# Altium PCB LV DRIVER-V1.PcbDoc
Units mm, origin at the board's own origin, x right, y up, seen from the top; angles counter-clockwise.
Board outline 70 x 80 mm, 2 copper layers (Top Layer, Bottom Layer); 48 components, 36 nets, 156 pads, 149 vias.
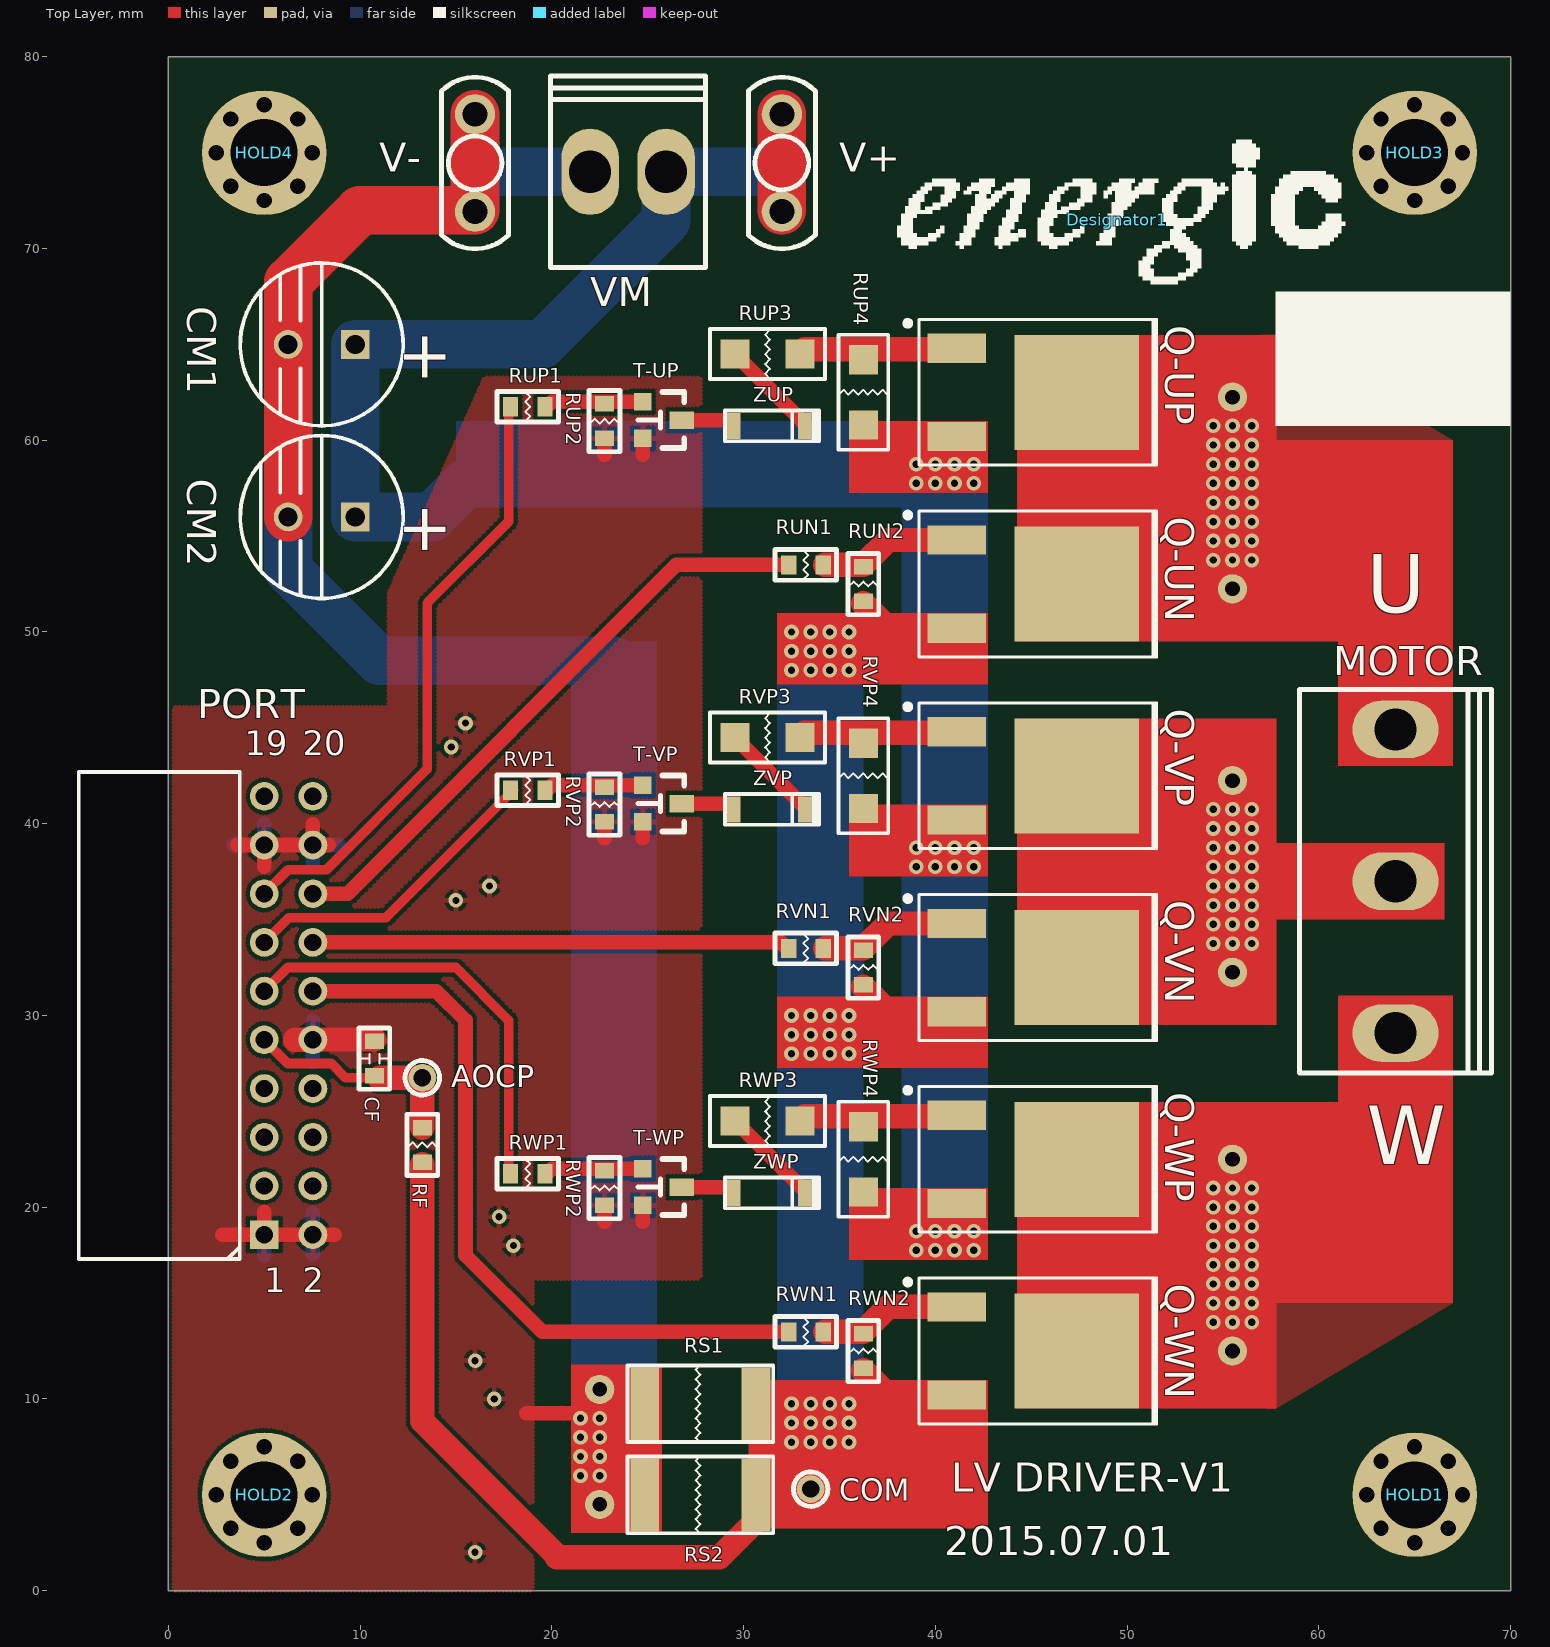
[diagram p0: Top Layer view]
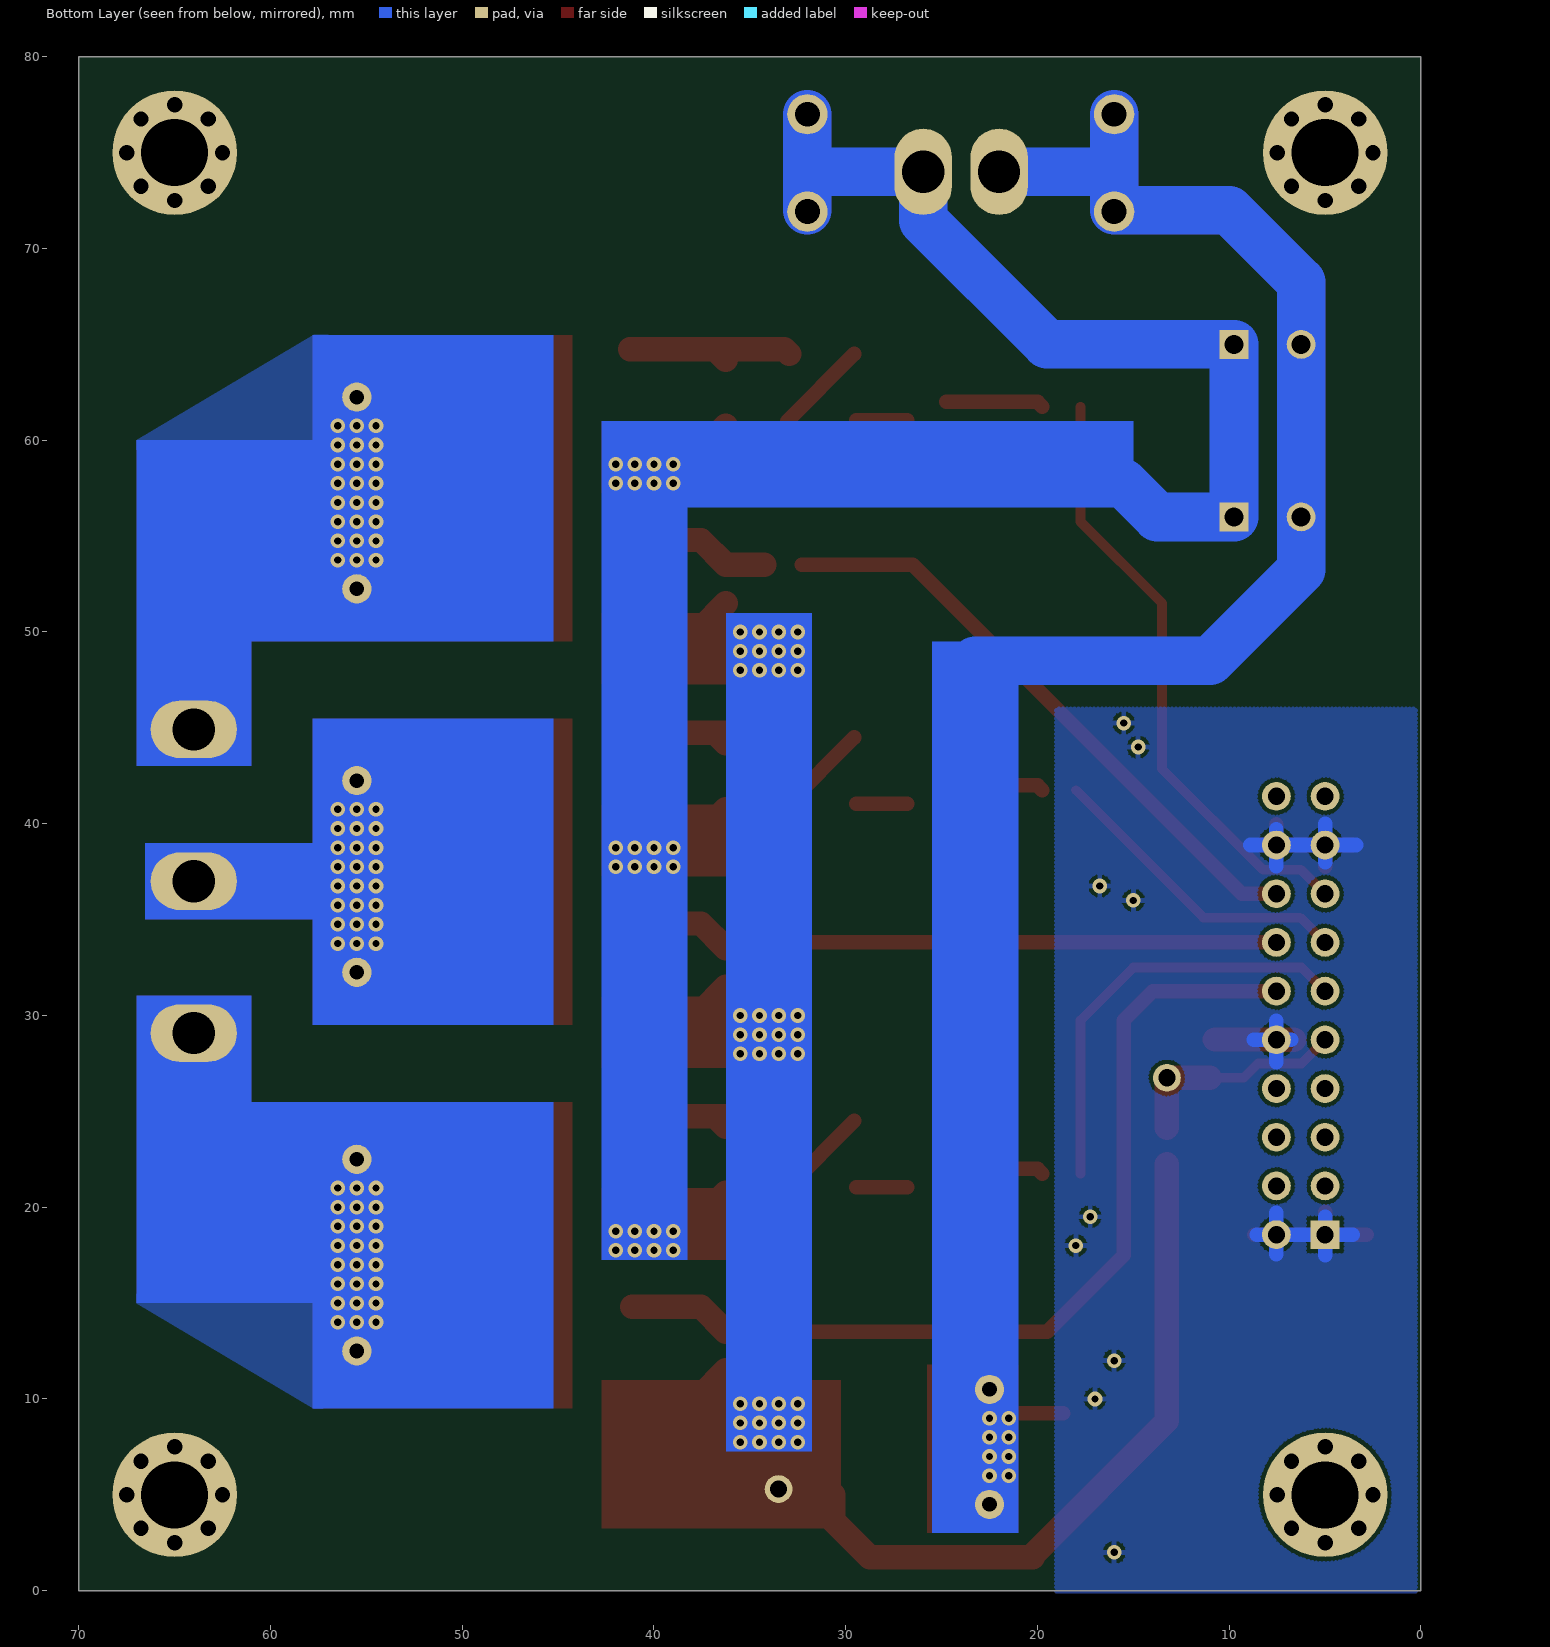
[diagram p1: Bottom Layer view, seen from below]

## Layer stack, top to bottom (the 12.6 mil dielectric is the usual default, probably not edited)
Top Layer: signal copper 0.0356
Dielectric: dielectric 0.32, FR-4, Dk 4.8
Bottom Layer: signal copper 0.0356

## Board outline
0,0 0,80 70,80 70,0

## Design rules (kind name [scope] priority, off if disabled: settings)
Clearance [All] p1: gap=0.203
MinimumSolderMaskSliver [All] p1: minsoldermaskwidth=0.127
PolygonConnect [All] p1: connectstyle=Relief reliefconductorwidth=0.254 reliefentries=4 polygonreliefangle="90 Angle"
RoutingVias [All] p1: holewidth=0.762 width=2.54 viastyle="Through Hole" minholewidth=0.203 minwidth=0.203 maxholewidth=0.711 maxwidth=1.27
SilkToSilkClearance [All] p1: silktosilkclearance=0.127
SilkscreenOverComponentPads [All] p1: minsilkscreentomaskgap=0
SolderMaskExpansion [All] p1: expansion=0.102
Width [All] p1: maxlimit=5.08 minlimit=0.254 preferedwidth=0.254
25 further rules are at their usual default settings.

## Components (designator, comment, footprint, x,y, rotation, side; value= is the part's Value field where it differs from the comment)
AOCP "" TP-R-0.9mm 13.25,26.75 r90 top
CF "1nF/50V/0603" C0603 10.75,27.75 r90 top
CM1 "220UF/35V/8*15" C-8MM-3.5PITCH 8,65 r270 top
CM2 "220UF/35V/8*15" C-8MM-3.5PITCH 8,56 r270 top
COM "" TP-R-0.9mm 33.5,5.3 r0 top
Designator1 "Comment" energic 49.5,71.5 r0 top
HOLD1 "TP" HOLD-3-6 65,5 r0 top
HOLD2 "TP" HOLD-3-6 5,5 r0 top locked
HOLD3 "TP" HOLD-3-6 65,75 r0 top
HOLD4 "TP" HOLD-3-6 5,75 r0 top
MOTOR "Header 5" CON-5-2P-3.96 64,37 r90 top
PORT "CON20/2.5/90" CON-2.54-2x20-90 5,18.57 r0 top locked
Q-UN "NMOS" TO-252 44.25,52.5 r180 top locked
Q-UP "PMOS" TO-252 44.25,62.5 r180 top locked
Q-VN "NMOS" TO-252 44.25,32.5 r180 top
Q-VP "PMOS" TO-252 44.25,42.5 r180 top
Q-WN "NMOS" TO-252 44.25,12.5 r180 top
Q-WP "PMOS" TO-252 44.25,22.5 r180 top
RF "100R/0603" R0603 13.25,23.25 r270 top
RS1 "0R1/2W" R2512 27.75,9.75 r180 top
RS2 "0R1/2W" R2512 27.75,5 r180 top
RUN1 "100/0603" R0603 33.25,53.5 r180 top
RUN2 "4.7K/0603" R0603 36.25,52.5 r270 top
RUP1 "1K/0603" R0603 18.75,61.75 r180 top
RUP2 "4.7K/0603" R0603 22.75,61 r270 top
RUP3 "100/1206" R1206 31.25,64.5 r0 top
RUP4 "470/1206" R1206 36.25,62.5 r270 top
RVN1 "100/0603" R0603 33.25,33.5 r180 top (schematic designator RUN1)
RVN2 "4.7K/0603" R0603 36.25,32.5 r270 top (schematic designator RUN2)
RVP1 "1K/0603" R0603 18.75,41.75 r180 top
RVP2 "4.7K/0603" R0603 22.75,41 r270 top (schematic designator RUP2)
RVP3 "100/1206" R1206 31.25,44.5 r0 top (schematic designator RUP3)
RVP4 "470/1206" R1206 36.25,42.5 r270 top (schematic designator RUP4)
RWN1 "100/0603" R0603 33.25,13.5 r180 top (schematic designator RUN1)
RWN2 "4.7K/0603" R0603 36.25,12.5 r270 top (schematic designator RUN2)
RWP1 "1K/0603" R0603 18.75,21.75 r180 top (schematic designator RUP1)
RWP2 "4.7K/0603" R0603 22.75,21 r270 top (schematic designator RUP2)
RWP3 "100/1206" R1206 31.25,24.5 r0 top (schematic designator RUP3)
RWP4 "470/1206" R1206 36.25,22.5 r270 top (schematic designator RUP4)
T-UP "MMBT4401" Q-MMBT4401 24.75,62 r180 top
T-VP "MMBT4401" Q-MMBT4401 24.75,42 r180 top (schematic designator T-UP)
T-WP "MMBT4401" Q-MMBT4401 24.75,22 r180 top (schematic designator T-UP)
V+ "(250T)" CON-P-850 32,77 r270 top
V- "(250T)" CON-P-850 16,77 r270 top
VM "Header 2" CON-2P-3.96 22,74 r180 top
ZUP "MMSZ 5242B T/R7" D-SOD123 29.5,60.75 r0 top
ZVP "MMSZ 5242B T/R7" D-SOD123 29.5,40.75 r0 top (schematic designator ZUP)
ZWP "MMSZ 5242B T/R7" D-SOD123 29.5,20.75 r0 top (schematic designator ZUP)

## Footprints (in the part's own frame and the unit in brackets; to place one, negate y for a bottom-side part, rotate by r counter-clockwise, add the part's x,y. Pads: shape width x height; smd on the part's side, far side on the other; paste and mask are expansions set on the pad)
C0603 [mm]
  rect 0.8x1 smd: 1(-0.9,0) 2(0.9,0)
  silkscreen extent -1.6,-0.8 1.6,0.8
C-8MM-3.5PITCH [mm]
  rect 1.5x1.5 hole 1: 1(0,1.75)
  round 1.5 hole 1: 2(0,-1.75)
  silkscreen extent -4.25,-4.25 4.25,4.25
CON-2.54-2x20-90 [mm] "Connector; Header; 10x2 Position; Right Angle"
  rect 1.5x1.5 hole 0.9: 1(0,0)
  round 1.5 hole 0.9: 2(2.54,0) 3(0,2.54) 4(2.54,2.54) 5(0,5.08) 6(2.54,5.08) 7(0,7.62) 8(2.54,7.62) 9(0,10.16) 10(2.54,10.16) 11(0,12.7) 12(2.54,12.7) 13(0,15.24) 14(2.54,15.24) 15(0,17.78) 16(2.54,17.78) 17(0,20.32) 18(2.54,20.32) 19(0,22.86) 20(2.54,22.86)
  silkscreen extent -9.67,-1.27 -1.27,24.13
CON-2P-3.96 [mm]
  oval 3x4.5 hole 2.2: 1(-3.96,0) 2(0,0)
  silkscreen extent -6.02,-5 2.06,5
CON-5-2P-3.96 [mm]
  oval 3x4.5 hole 2.2: 1(-7.92,0) 3(0,0) 5(7.92,0)
  silkscreen extent -10,-5 10,5
CON-P-850 [mm]
  round 2.1 hole 1.3: 1(0,0) 1(5.08,0)
  silkscreen extent -1.93,-1.75 7.01,1.75
D-SOD123 [mm]
  rect 0.7x1.35 smd: A(0,0) K(3.7,0)
  silkscreen extent -0.47,-0.8 4.43,0.8
energic [mm]
  silkscreen extent -11.48,-3.35 11.89,4.17
HOLD-3-6 [mm]
  round 1.2 hole 0.8: 1(-2.5,0) 1(-1.75,-1.75) 1(-1.75,1.75) 1(-0.004,2.5) 1(0,-2.5) 1(1.75,-1.75) 1(1.75,1.75) 1(2.5,0)
  round 6.5 hole 3.5: 1(0,0)
Q-MMBT4401 [mil]
  rect 36x36 smd: B(0,0) E(0,75)
  rect 50x36 smd: C(-80,37.5)
  silkscreen extent -85,-20 10,95
R0603 [mm]
  rect 0.8x1 smd: 1(-0.9,0) 2(0.9,0)
  silkscreen extent -1.6,-0.8 1.6,0.8
R1206 [mil]
  rect 60x60 smd: 1(66.93,0) 2(-66.93,0)
  silkscreen extent -118,-51 118,51
R2512 [mm]
  rect 1.5x3.8 smd: 1(2.9,0) 2(-2.9,0)
  silkscreen extent -3.8,-2.03 3.8,2.03
TO-252 [mm]
  rect 6.5x6 smd: D(-3.125,0)
  rect 3.048x1.524 smd: G(3.125,-2.3) S(3.125,2.3)
  silkscreen extent -7.3,-3.8 5.81,3.8
TP-R-0.9mm [mm]
  round 1.45 hole 0.9: 1(0,0)
  silkscreen extent -0.9,-0.9 0.9,0.9

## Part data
AOCP COM: library part "TEST POINT", "TEST POINT"
CF: library part 1000PF/50V/0603, "1000pF(102)(1n),50V,∮10%,X7R,0603,PSA"
CM1 CM2: library part 100UF/25V/6.3*11, "100uF,25V,LowRES,6.3*11mm,Pitch:2.5,DIP,KY-SERIES"
HOLD1 HOLD2 HOLD3 HOLD4 V+ V-: library part CON1, "Connector"
MOTOR: "Header, 5-Pin"
PORT: library part "Header 10X2H", "Header, 10-Pin, Dual row, Right Angle"
Q-UN Q-VN Q-WN: "N-Channel Power MOSFET"
Q-UP Q-VP Q-WP: "P-Channel Power MOSFET"
RF: library part 100R/06, "100R,1%,0603,PSA,¥@·"
RS1 RS2: library part RES1
RUN1 RUN2 RUP1 RUP2 RUP3 RUP4 RVN1 RVN2 RVP1 RVP2 RVP3 RVP4 RWN1 RWN2 RWP1 RWP2 RWP3 RWP4: library part 1M/0603
T-UP T-VP T-WP: library part NPN, "NPN Transistor"
VM: "Header, 2-Pin"
ZUP ZVP ZWP: library part ZENER2, "Zener Diode"

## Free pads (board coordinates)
  round 1.524 hole 0.762: 107(22.5,4.5) 107(22.5,10.5) 107(55.5,12.5) 107(55.5,22.5) 107(55.5,32.25) 107(55.5,42.25) 107(55.5,52.25) 107(55.5,62.25)

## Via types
v1: diameter 0.762, hole 0.381, Top Layer to Bottom Layer, 149 vias

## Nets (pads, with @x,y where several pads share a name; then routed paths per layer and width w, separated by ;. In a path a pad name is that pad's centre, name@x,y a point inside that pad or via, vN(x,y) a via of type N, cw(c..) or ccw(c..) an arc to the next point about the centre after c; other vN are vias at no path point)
AOCP: AOCP.1 CF.1 PORT.9 RF.1 | length 11.7
  Top Layer w0.508: PORT.9 6.23,27.5 8.5,27.5 9.25,26.75 CF.1@11,26.75
  Top Layer w1.27: CF.1@11,26.75 AOCP.1 RF.1
CH2: PORT.7
CH3: PORT.8
CH4: PORT.5
CH5: PORT.6
CH6: PORT.3
CH7: PORT.4
COM: COM.1 Q-UN.S Q-VN.S Q-WN.S RF.2 RS1.2 RS2.2 RUN2.2 RVN2.2 RWN2.2 | length 52.2
  Top Layer w1.27: RF.2@13.25,22.25 13.25,8.85 20.35,1.75 ; 20.25,1.75 28.75,1.75 30.65,3.65 RS2.2 ; RWN2.2@36.25,11.5 37.55,10.2 Q-WN.S ; RVN2.2@36.25,31.5 37.55,30.2 Q-VN.S ; RUN2.2@36.25,51.5 37.55,50.2 Q-UN.S
  other v1: 32.5,7.75 33.5,7.75 34.5,7.75 35.5,7.75 32.5,8.75 33.5,8.75 34.5,8.75 35.5,8.75 32.5,9.75 33.5,9.75 34.5,9.75 35.5,9.75 32.5,28 33.5,28 34.5,28 35.5,28 32.5,29 33.5,29 34.5,29 35.5,29 32.5,30 33.5,30 34.5,30 35.5,30 32.5,48 33.5,48 34.5,48 35.5,48 32.5,49 33.5,49 34.5,49 35.5,49 32.5,50 33.5,50 34.5,50 35.5,50
MU: MOTOR.5 pad.107@55.5,52.25 pad.107@55.5,62.25 Q-UN.D Q-UP.D
  other v1: 54.5,53.75 55.5,53.75 56.5,53.75 54.5,54.75 55.5,54.75 56.5,54.75 54.5,55.75 55.5,55.75 56.5,55.75 54.5,56.75 55.5,56.75 56.5,56.75 54.5,57.75 55.5,57.75 56.5,57.75 54.5,58.75 55.5,58.75 56.5,58.75 54.5,59.75 55.5,59.75 56.5,59.75 54.5,60.75 55.5,60.75 56.5,60.75
MV: MOTOR.3 pad.107@55.5,32.25 pad.107@55.5,42.25 Q-VN.D Q-VP.D
  other v1: 54.5,33.75 55.5,33.75 56.5,33.75 54.5,34.75 55.5,34.75 56.5,34.75 54.5,35.75 55.5,35.75 56.5,35.75 54.5,36.75 55.5,36.75 56.5,36.75 54.5,37.75 55.5,37.75 56.5,37.75 54.5,38.75 55.5,38.75 56.5,38.75 54.5,39.75 55.5,39.75 56.5,39.75 54.5,40.75 55.5,40.75 56.5,40.75
MW: MOTOR.1 pad.107@55.5,12.5 pad.107@55.5,22.5 Q-WN.D Q-WP.D
  other v1: 54.5,14 55.5,14 56.5,14 54.5,15 55.5,15 56.5,15 54.5,16 55.5,16 56.5,16 54.5,17 55.5,17 56.5,17 54.5,18 55.5,18 56.5,18 54.5,19 55.5,19 56.5,19 54.5,20 55.5,20 56.5,20 54.5,21 55.5,21 56.5,21
NetQ-UN_G: Q-UN.G RUN1.1 RUN2.1 | length 7.4
  Top Layer w1.27: RUN1.1@34.25,53.5 36.25,53.5 37.55,54.8 Q-UN.G
NetQ-UP_G: Q-UP.G RUP3.1 RUP4.2 | length 9.2
  Top Layer w1.27: RUP3.1 33.2,64.75 RUP4.2@36.8,64.75 ; RUP4.2 RUP4.2@36.8,64.75 ; Q-UP.G@41.25,64.75 RUP4.2@36.8,64.75
NetQ-VN_G: Q-VN.G RVN1.1 RVN2.1 | length 7.4
  Top Layer w1.27: RVN1.1@34.25,33.5 36.25,33.5 37.55,34.8 Q-VN.G
NetQ-VP_G: Q-VP.G RVP3.1 RVP4.2 | length 9.2
  Top Layer w1.27: RVP3.1 33.2,44.75 RVP4.2@36.8,44.75 ; RVP4.2 RVP4.2@36.8,44.75 ; Q-VP.G@41.25,44.75 RVP4.2@36.8,44.75
NetQ-WN_G: Q-WN.G RWN1.1 RWN2.1 | length 7.4
  Top Layer w1.27: RWN1.1@34.25,13.5 36.25,13.5 37.55,14.8 Q-WN.G
NetQ-WP_G: Q-WP.G RWP3.1 RWP4.2 | length 9.2
  Top Layer w1.27: RWP3.1 33.2,24.75 RWP4.2@36.8,24.75 ; RWP4.2 RWP4.2@36.8,24.75 ; Q-WP.G@41.25,24.75 RWP4.2@36.8,24.75
NetRUP1_1: RUP1.1 RUP2.1 T-UP.B | length 5.1
  Top Layer w0.762: RUP1.1@19.75,61.75 20,62 T-UP.B
NetRUP3_2: RUP3.2 ZUP.K | length 4.9
  Top Layer w0.762: RUP3.2 ZUP.K@33.05,61
NetRVP1_1: RVP1.1 RVP2.1 T-VP.B | length 5.1
  Top Layer w0.762: RVP1.1@19.75,41.75 20,42 T-VP.B
NetRVP3_2: RVP3.2 ZVP.K | length 4.9
  Top Layer w0.762: RVP3.2 ZVP.K@33.05,41
NetRWP1_1: RWP1.1 RWP2.1 T-WP.B | length 5.1
  Top Layer w0.762: RWP1.1@19.75,21.75 20,22 T-WP.B
NetRWP3_2: RWP3.2 ZWP.K | length 4.9
  Top Layer w0.762: RWP3.2 ZWP.K@33.05,21
NetT-UP_C: T-UP.C ZUP.A | length 2.7
  Top Layer w0.762: T-UP.C ZUP.A@29.453,61.048
NetT-VP_C: T-VP.C ZVP.A | length 2.7
  Top Layer w0.762: T-VP.C ZVP.A@29.453,41.047
NetT-WP_C: T-WP.C ZWP.A | length 2.7
  Top Layer w0.762: T-WP.C ZWP.A@29.453,21.048
PGND: CF.2 CM1.2 CM2.2 pad.107@22.5,4.5 pad.107@22.5,10.5 PORT.1 PORT.2 PORT.10 PORT.17 PORT.18 RS1.1 RS2.1 RUP2.2 RVP2.2 RWP2.2 T-UP.E T-VP.E T-WP.E V-.1 VM.2 | length 136.3
  Top Layer w0.762: 2.82,18.57 PORT.1 ; 3.61,38.89 PORT.17 ; 5,19.75 PORT.1 ; 5,37.75 PORT.17 ; 7.54,39.96 PORT.18 ; 8.355,38.89 PORT.18 ; 8.68,18.57 PORT.2 PORT.1 ; 18.669,9.25 v1@21.5,9.25 ; 22.75,19.25 RWP2.2 ; 22.75,39.25 RVP2.2 ; 22.75,59.25 RUP2.2 ; 24.75,19.25 T-WP.E ; 24.75,39.25 T-VP.E ; 24.75,59.25 T-UP.E ; PORT.17 PORT.18
  Top Layer w1.27: 6.608,28.73 PORT.10 7.56,28.75 CF.2@10.75,28.75
  Top Layer w2.54: CM2.2 CM1.2 6.25,68.25 10,72 16,72 V-.1@16,77
  Bottom Layer w0.762: 3.39,38.89 PORT.17 ; 3.57,18.57 PORT.1 ; 5,17.5 PORT.1 ; 5,19.5 PORT.1 ; 5,38 PORT.17 ; 5,40 PORT.17 ; 6.77,28.73 PORT.10 ; 7.54,17.54 PORT.2 ; 7.54,19.71 PORT.2 ; 7.54,27.564 PORT.10 ; 7.54,29.71 PORT.10 ; 7.54,37.79 PORT.18 ; 7.54,39.71 PORT.18 ; 8.57,18.57 PORT.2 ; 8.73,28.73 PORT.10 ; 8.89,38.89 PORT.18 ; PORT.1 PORT.2 ; PORT.17 PORT.18
  Bottom Layer w2.032: V-.1@15.75,72 V-.1@16,72
  Bottom Layer w2.54: 16,74 VM.2 ; 16,74.5 16,77 16,72 10,72 6.25,68.25 CM1.2 CM2.2 6.25,53.25 11,48.5 23.25,48.5
  other v1: 16,2 21.5,6 22.5,6 21.5,7 22.5,7 21.5,8 22.5,8 21.5,9 22.5,9 17,10 16,12 18,18 17.25,19.5 15,36 16.75,36.75 14.75,44 15.5,45.25
S5V: PORT.20
S15V: PORT.19
UN: PORT.16 RUN1.2 | length 31.9
  Top Layer w0.762: PORT.16 9.35,36.35 26.5,53.5 RUN1.2@32.3,53.5
UP: PORT.15 RUP1.2 | length 31.9
  Top Layer w0.508: PORT.15 6.25,37.6 8.25,37.6 13.5,42.85 13.5,51.5 17.75,55.75 RUP1.2@17.75,61.75
VM: CM1.1 CM2.1 Q-UP.S Q-VP.S Q-WP.S RUP4.1 RVP4.1 RWP4.1 V+.1 VM.1 | length 68
  Top Layer w1.27: RWP4.1@36.25,20.75 36.8,20.2 Q-WP.S ; RVP4.1@36.25,40.75 36.8,40.2 Q-VP.S ; RUP4.1@36.25,60.75 36.8,60.2 Q-UP.S
  Top Layer w2.54: V+.1@32,72 V+.1@32,77
  Bottom Layer w2.54: 15.5,57.75 13.75,56 CM2.1 CM1.1 19.5,65 25.96,71.46 VM.1 31.75,74 ; V+.1@32,72 V+.1@32,77
  other v1: 39,17.75 40,17.75 41,17.75 42,17.75 39,18.75 40,18.75 41,18.75 42,18.75 39,37.75 40,37.75 41,37.75 42,37.75 39,38.75 40,38.75 41,38.75 42,38.75 39,57.75 40,57.75 41,57.75 42,57.75 39,58.75 40,58.75 41,58.75 42,58.75
VN: PORT.14 RVN1.2 | length 24.8
  Top Layer w0.762: PORT.14 31.94,33.81 RVN1.2@32.25,33.5
VP: PORT.13 RVP1.2 | length 16.3
  Top Layer w0.508: PORT.13 6.29,35.1 11.35,35.1 RVP1.2@18,41.75
WN: PORT.12 RWN1.2 | length 41.4
  Top Layer w0.762: PORT.12 13.98,31.27 ; RWN1.2@32.25,13.5 19.5,13.5 15.5,17.5 15.5,29.75 ; 13.98,31.27 15.5,29.75 ; 13.98,31.27 15.5,29.75
WP: PORT.11 RWP1.2 | length 22.4
  Top Layer w0.508: PORT.11 6.23,32.5 15,32.5 17.75,29.75 17.75,28.75 RWP1.2@17.75,21.75
pads on no net: HOLD1.1 HOLD2.1 HOLD3.1 HOLD4.1

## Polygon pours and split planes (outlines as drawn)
PGND on Top Layer "Bottom Layer-No Net" (hatched 90Degree grid 0.203 track 0.254, remove dead copper, pour order 14): 0.286,46.053 0.286,0.025 19,0.025 19,46.053
MU on Top Layer "Top Layer-No Net" (solid, pour order 11): 57.75,65.5 67,60 67,59.5 57,59.5 57,65.5
MW on Top Layer "Top Layer-No Net" (solid, pour order 10): 67,15.5 67,15 57.75,9.5 57.25,9.5 57.25,15.5
PGND on Top Layer "Bottom Layer-No Net" (hatched 90Degree grid 0.203 track 0.254, remove dead copper, pour order 13): 16.5,63.25 11.5,52 11.5,16.275 27.75,16.275 27.75,63.25
MW on Bottom Layer "Top Layer-No Net" (solid, pour order 9): 67,15.5 67,15 57.75,9.5 57.25,9.5 57.25,15.5
MU on Bottom Layer "Top Layer-No Net" (solid, pour order 8): 57.75,65.5 67,60 67,59.5 57,59.5 57,65.5
PGND on Bottom Layer "Bottom Layer-No Net" (hatched 90Degree grid 0.203 track 0.254, remove dead copper, pour order 12): 0.286,46 0.286,-0.028 19,-0.028 19,46

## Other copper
Top Layer:
  rectangle net VM: 35.5,57.25 42.75,61
  rectangle net COM: 31.75,47.25 42.75,51
  rectangle net MU: 44.25,49.5 57.8,65.5
  rectangle net COM: 31.75,27.25 42.75,31
  rectangle net COM: 30.25,3.25 42.75,11
  rectangle net VM: 35.5,17.25 42.75,21
  rectangle net VM: 35.5,37.25 42.75,41
  region net PGND: 25.75,3 25.75,11.8 21,11.8 21,3
  rectangle net MV: 44.25,29.5 57.8,45.5
  rectangle net MW: 44.25,9.5 57.8,25.5
  rectangle net MV: 53,35 66.55,39
  region net MW: 67,15 67,25.5 56,25.5 56,15
  region net MW: 67,17.5 67,31.05 61,31.05 61,17.5
  region net MU: 67,49.5 67,60 56,60 56,49.5
  region net MU: 67,43 67,56.55 61,56.55 61,43
Bottom Layer:
  rectangle net VM: 38.25,17.25 42.75,61
  rectangle net COM: 31.75,7.25 36.25,51
  rectangle net PGND: 21,3 25.5,49.5
  rectangle net MV: 45.25,29.5 57.8,45.5
  rectangle net MU: 45.25,49.5 57.8,65.5
  rectangle net MW: 45.25,9.5 57.8,25.5
  rectangle net MV: 53,35 66.55,39
  region net MW: 67,15 67,25.5 56,25.5 56,15
  region net MW: 67,17.5 67,31.05 61,31.05 61,17.5
  region net MU: 67,49.5 67,60 56,60 56,49.5
  region net MU: 67,43 67,56.55 61,56.55 61,43
  region net VM: 42.75,56.5 42.75,61 15,61 15,56.5

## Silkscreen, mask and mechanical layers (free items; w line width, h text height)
Top Overlay:
  rectangle: 57.75,60.75 70,67.75
  text "U" at 62.5,51 h3.05
  text "W" at 62.5,22.25 h3.05
  text "LV DRIVER-V1" at 40.822,5.154 h1.52
  text "2015.07.01" at 40.466,1.852 h1.52
Mechanical 1:
  the board outline again, w0.254
Drill Drawing:
  text ".Legend" at 74,2 h1.52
